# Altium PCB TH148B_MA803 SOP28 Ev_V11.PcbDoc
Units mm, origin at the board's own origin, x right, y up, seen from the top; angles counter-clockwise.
Board outline 72.39 x 53.59 mm, 2 copper layers (Top Layer, Bottom Layer); 44 components, 47 nets, 236 pads, 91 vias.
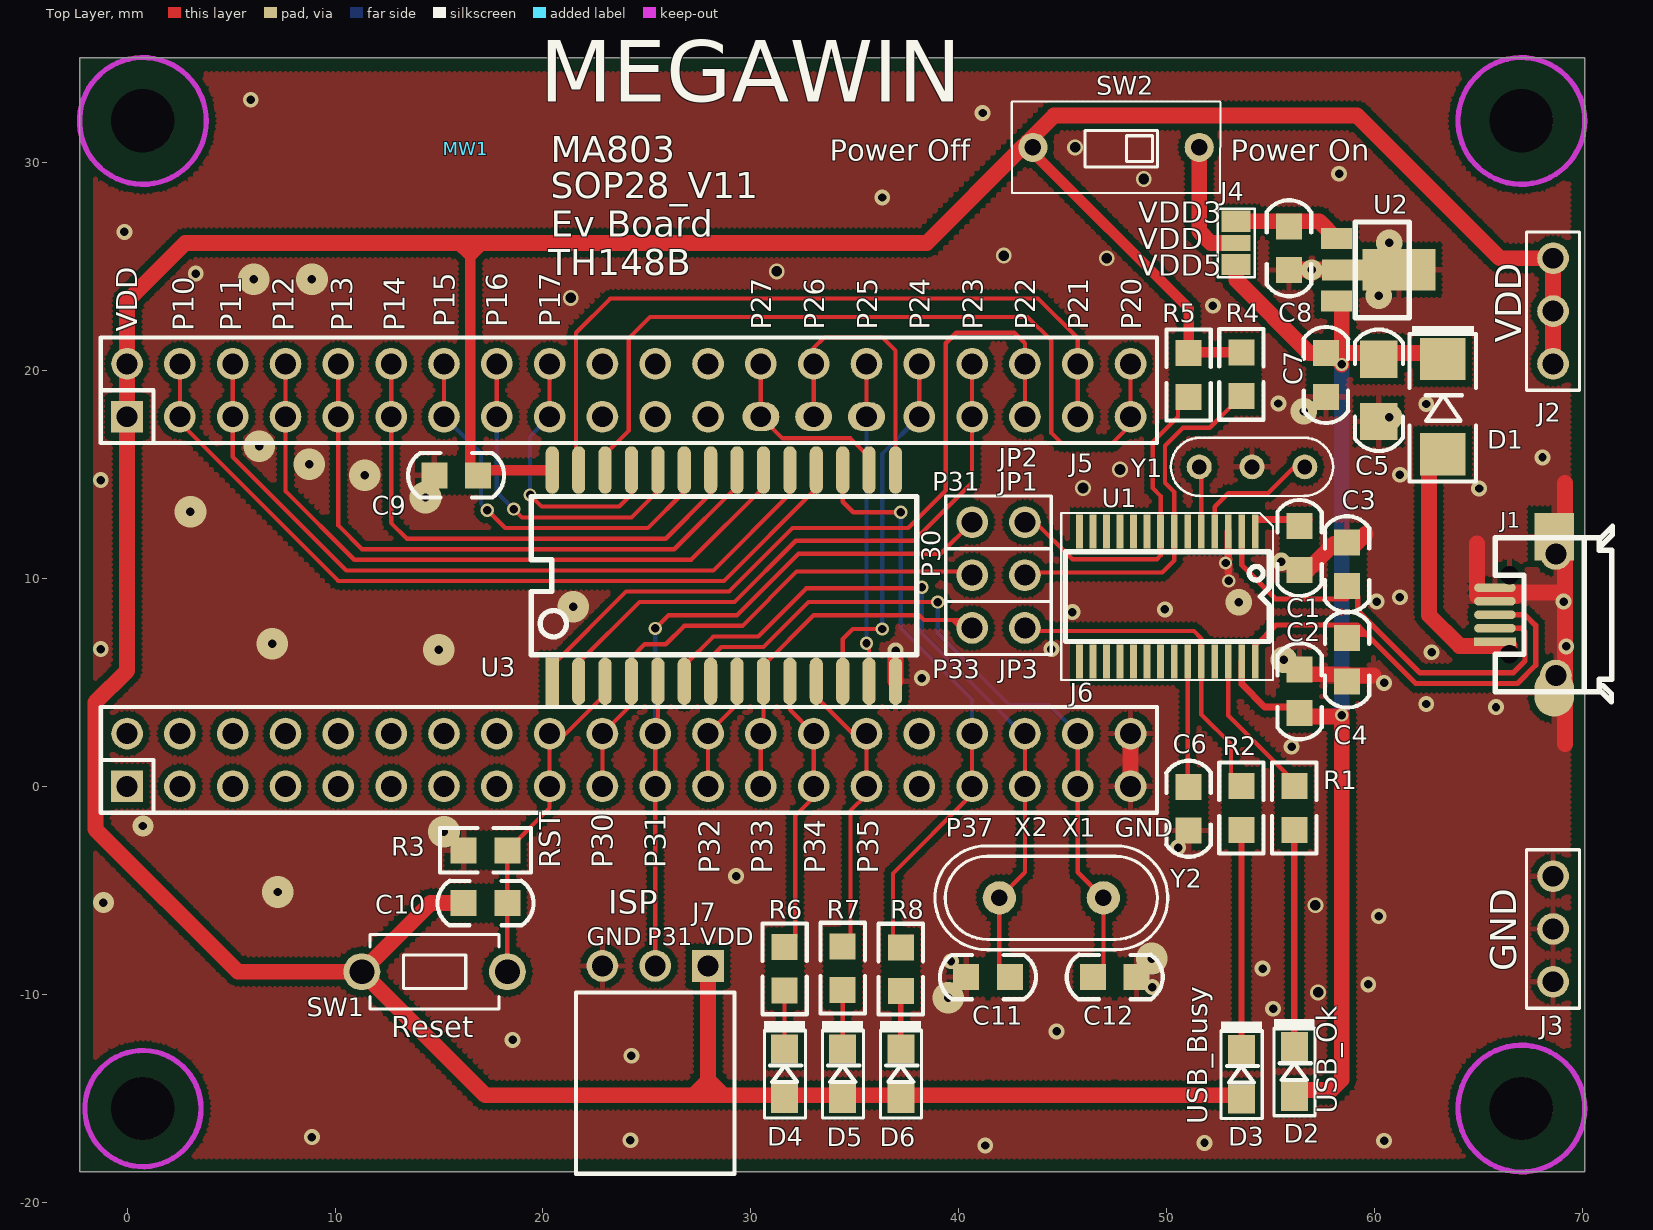
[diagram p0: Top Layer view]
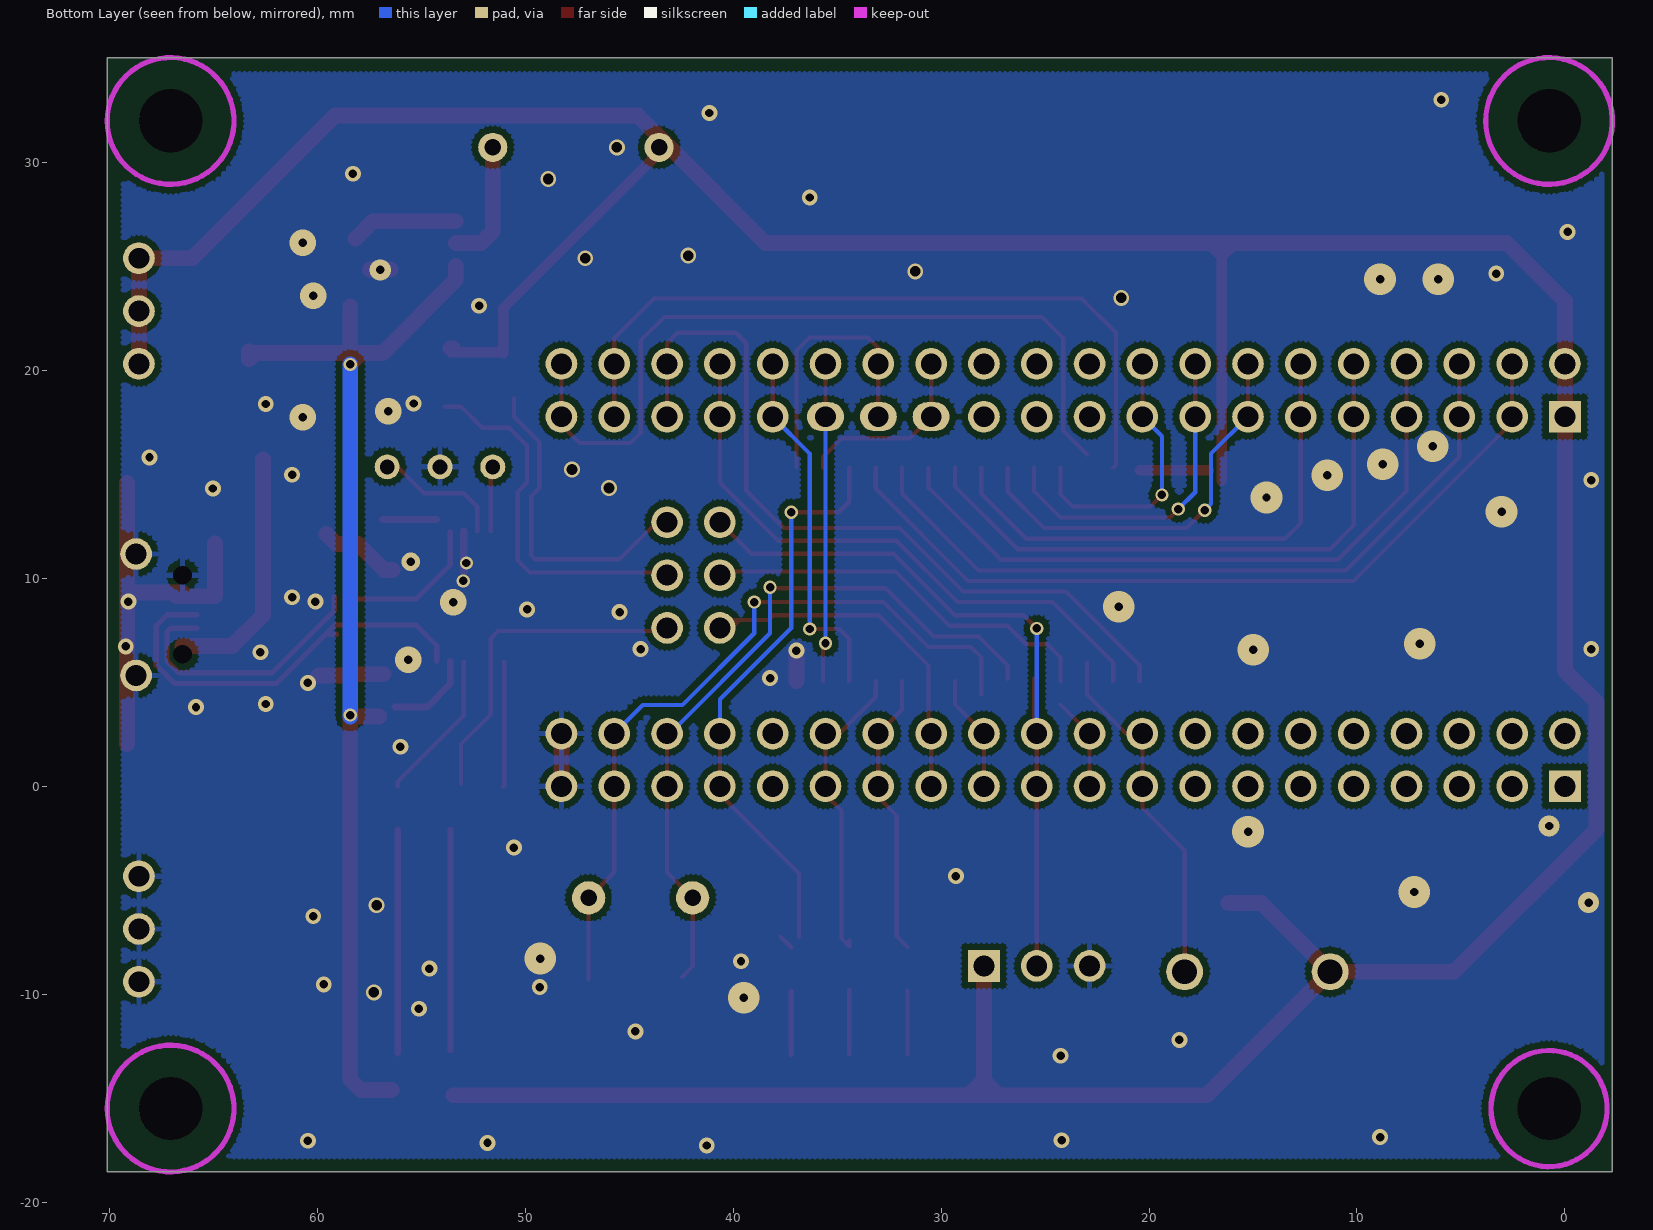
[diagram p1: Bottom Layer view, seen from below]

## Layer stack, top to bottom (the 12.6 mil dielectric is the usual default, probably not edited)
Top Layer: signal copper 0.0356
Dielectric: dielectric 0.32, FR-4, Dk 4.8
Bottom Layer: signal copper 0.0356

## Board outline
-2.286,-18.542 -2.286,35.052 70.104,35.052 70.104,-18.542

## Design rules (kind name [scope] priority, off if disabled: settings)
Clearance 12 [All] p1 off: gap=0.305
Clearance 10 [All] p2 off: gap=0.254
Clearance 6 [All] p3: gap=0.152
ComponentClearance [All] p1 off: gap=0.254 collisioncheckmode=3 verticalgap=0.254 showdistances=FALSE
HoleSize [All] p1: absolutevalues=TRUE maxlimit=12.7 minlimit=0.025 maxpercent=80.000 minpercent=20.000
MinimumSolderMaskSliver [All] p1 off: minsoldermaskwidth=0.254
PolygonConnect VIA [ISVIA] p1: connectstyle=Direct reliefconductorwidth=0.254 reliefentries=4 polygonreliefangle="90 Angle"
PolygonConnect [All] p2: connectstyle=Relief reliefconductorwidth=0.254 reliefentries=4 polygonreliefangle="90 Angle"
RoomDefinition "TH148B_MA803 SOP28 Ev_V10" [InComponentClass('TH148B_MA803 SOP28 Ev_V10')] p1: confinementstyle=ConfineIn formatcopy=TRUE lockcomponents=FALSE outline -6.35,-23.622 77.724,-23.622 77.724,42.291 -6.35,42.291
RoutingVias [All] p1: holewidth=0.406 width=0.635 viastyle="Through Hole" minholewidth=0.406 minwidth=0.61 maxholewidth=0.711 maxwidth=1.27
SilkToSilkClearance [All] p1 off: silktosilkclearance=0.254
SilkscreenOverComponentPads [All] p1 off: minsilkscreentomaskgap=0.254
SolderMaskExpansion [All] p1 off: expansion=0.102
Width [All] p1: maxlimit=5.08 minlimit=0.152 preferedwidth=0.254
23 further rules are at their usual default settings.

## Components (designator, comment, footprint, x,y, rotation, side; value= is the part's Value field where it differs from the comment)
C1 "4.7uF" 0805C 56.388,11.464 r270 top
C2 "0.1uF" 0805C 56.388,4.572 r270 top
C3 "15pF" 0805C 58.674,10.686 r90 top
C4 "15pF" 0805C 58.674,6.096 r270 top
C5 "4.7uF" 1206C 60.198,19.05 r270 top
C6 "0.1uF" 0805C 51.054,-1.075 r90 top
C7 "0.1uF" 0805C 57.658,19.787 r270 top
C8 "4.7uF" 0805C 55.88,25.883 r270 top
C9 "0.1uF" 0805C 15.824,14.961 r180 top
C10 "1u" 0805C 17.238,-5.613 r0 top
C11 "NC" 0805C 41.402,-9.169 r180 top
C12 "NC" 0805C 47.498,-9.169 r0 top
D1 "1N5817" D5817_SMD_1 63.28,18.263 r270 top
D2 "Yellow" 0805D 56.134,-13.716 r90 top
D3 "RED" 0805D 53.594,-13.843 r90 top
D4 "Green" 0805D 31.623,-13.82 r90 top
D5 "RED" 0805D 34.417,-13.82 r90 top
D6 "Green" 0805D 37.211,-13.82 r90 top
J1 "Micro USB母座" JACK_USB_SMD290X220P065 65.786,8.255 r180 top
J2 "*" PS3P254 68.58,20.32 r90 top
J3 "*" PS3P254 68.58,-4.318 r270 top
J4 "*" JUMP3_SMD 53.34,26.137 r90 top
J5 "*" PS20X2P254#1 0,17.78 r0 top locked
J6 "*" PS20X2P254#2 0,0 r0 top locked
J7 "*" PS3P254f_90 27.94,-8.636 r180 top
JP1 "JUMPER2" PS2P254 40.64,10.16 r0 top
JP2 "JUMPER2" PS2P254 40.64,12.7 r0 top
JP3 "JUMPER2" PS2P254 40.64,7.62 r0 top
MW1 "MW-A4" MEGAWIN_T 16.286,30.663 r0 top
R1 "1K" 0805R 56.134,-1.041 r270 top
R2 "1K" 0805R 53.594,-1.041 r270 top
R3 "47K" 0805R 17.238,-3.073 r0 top
R4 "4.7K" 0805R 53.594,19.821 r270 top
R5 "4.7K" 0805R 51.054,19.787 r270 top
R6 "1K" 0805R 31.623,-8.774 r270 top
R7 "1K" 0805R 34.417,-8.74 r270 top
R8 "1K" 0805R 37.211,-8.788 r270 top
SW1 "SW TACT-SPST" SW_T_2P 14.788,-8.915 r0 top
SW2 "-" DIP2_SW 51.562,30.734 r180 top
U1 "MA101_TSSOP28" TSSOP28_170P065 50.034,9.132 r180 top
U2 "AIC1734-33(SOT-89)" SOT89 58.166,24.843 r270 top
U3 "MA803 (SOP-28)" SO28_300P127 28.702,10.135 r0 top locked
Y1 "6MHz" X3P 56.642,15.367 r180 top (schematic designator X1)
Y2 "NC" X49U 44.45,-5.359 r0 top (schematic designator X2)

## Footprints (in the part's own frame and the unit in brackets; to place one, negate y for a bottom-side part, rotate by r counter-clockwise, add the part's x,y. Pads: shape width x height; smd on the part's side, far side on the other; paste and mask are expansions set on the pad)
0805C [mm]
  rect 1.25x1.25 smd: 1(-1.05,0) 2(1.05,0)
  silkscreen extent -2.31,-1.07 2.31,1.07
0805D [mm]
  rect 1.4x1.3 smd: 1(-1.192,0) 2(1.192,0)
  silkscreen extent -2.12,-1 2.53,0.98
0805R [mm]
  rect 1.25x1.25 smd: 1(-1.05,0) 2(1.05,0)
  silkscreen extent -2.18,-1.07 2.18,1.07
1206C [mm]
  rect 1.8x1.8 smd: 1(-1.5,0) 2(1.5,0)
  silkscreen extent -2.92,-1.15 2.92,1.16
D5817_SMD_1 [mil]
  rect 80x86.61 smd: 1(90,0) 2(-90,0)
  silkscreen extent -153,-63 142,63
DIP2_SW [mm]
  round 1.4 hole 0.8: 1(0,0) 2(8,0)
  silkscreen extent -1.02,-2.2 9.02,2.2
JACK_USB_SMD290X220P065 [mm]
  rect 1.9x1.8 on Mech2: 0(-2.85,-1.15) 0(-2.85,1.15)
  round 0.8 hole 0.9 unplated: 1(-0.7,1.9) 5(-0.7,-1.9)
  rect 2x0.4 smd: 1(0,1.3)
  oval 2x0.4 smd: 2(0,0.65) 3(0,0) 4(0,-0.65) 5(0,-1.3)
  round 1.524 hole 1: 5(-2.931,2.921) 5(-2.931,-2.921)
  oval 1.9x2.3 smd: 5(-2.85,3.75)
  rect 1.9x2.3 smd: 5(-2.85,-3.75)
  silkscreen extent -5.65,-4.25 -0.01,4.2
JUMP3_SMD [mil]
  rect 40x55 smd: 1(-41,0) 3(41,0)
  rect 30x55 smd: 2(0,0)
  silkscreen extent -65,-35 65,35
MEGAWIN_T [mm]
PS2P254 [mil]
  round 60 hole 39.37: 1(0,0) 2(100,0)
  silkscreen extent -50,-50 150,50
PS3P254 [mil]
  round 60 hole 39.37: 1(0,0) 2(100,0) 3(200,0)
  silkscreen extent -50,-50 250,50
PS3P254f_90 [mil]
  rect 60x60 hole 39.37: 1(0,0)
  round 60 hole 39.37: 2(100,0) 3(200,0)
  silkscreen extent -50,50 250,394
PS20X2P254#1 [mil]
  rect 60x60 hole 39.37: 1(0,0)
  round 60 hole 39.37: 2(0,100) 3(100,0) 4(100,100) 5(200,0) 6(200,100) 7(300,0) 8(300,100) 9(400,0) 10(400,100) 11(500,0) 12(500,100) 13(600,0) 14(600,100) 15(700,0) 16(700,100) 17(800,0) 18(800,100) 19(900,0) 20(900,100) 21(1000,0) 22(1000,100) 23(1100,0) 24(1100,100) 26(1200,100) 28(1300,100) 30(1400,100) 31(1500,0) 32(1500,100) 33(1600,0) 34(1600,100) 35(1700,0) 36(1700,100) 37(1800,0) 38(1800,100) 39(1900,0) 40(1900,100)
  oval 70x55 hole 39.37: 25(1200,0) 27(1300,0) 29(1400,0)
  silkscreen extent -50,-50 1950,150
PS20X2P254#2 [mil]
  rect 60x60 hole 39.37: 1(0,0)
  round 60 hole 39.37: 2(0,100) 3(100,0) 4(100,100) 5(200,0) 6(200,100) 7(300,0) 8(300,100) 9(400,0) 10(400,100) 11(500,0) 12(500,100) 13(600,0) 14(600,100) 15(700,0) 16(700,100) 17(800,0) 18(800,100) 19(900,0) 20(900,100) 21(1000,0) 22(1000,100) 23(1100,0) 24(1100,100) 25(1200,0) 26(1200,100) 27(1300,0) 28(1300,100) 29(1400,0) 30(1400,100) 31(1500,0) 32(1500,100) 33(1600,0) 34(1600,100) 35(1700,0) 36(1700,100) 37(1800,0) 38(1800,100) 39(1900,0) 40(1900,100)
  silkscreen extent -50,-50 1950,150
SO28_300P127 [mil]
  rect 25x90 smd: 1(-325,-200)
  oval 25x90 smd: 2(-275,-200) 3(-225,-200) 4(-175,-200) 5(-125,-200) 6(-75,-200) 7(-25,-200) 8(25,-200) 9(75,-200) 10(125,-200) 11(175,-200) 12(225,-200) 13(275,-200) 14(325,-200) 15(325,200) 16(275,200) 17(225,200) 18(175,200) 19(125,200) 20(75,200) 21(25,200) 22(-25,200) 23(-75,200) 24(-125,200) 25(-175,200) 26(-225,200) 27(-275,200) 28(-325,200)
  silkscreen extent -365,-150 365,150
SOT89 [mm]
  rect 1.016x1.5 smd: 1(-1.5,0) 3(1.5,0)
  rect 2x3.5 smd: 2(0,3)
  rect 1.016x2.6 smd: 2(0,0.6)
  silkscreen extent -2.3,0.9 2.3,3.5
SW_T_2P [mm]
  round 1.778 hole 1.2: 1(-3.5,0) 2(3.5,0)
  silkscreen extent -3.1,-1.8 3.1,1.8
TSSOP28_170P065 [mil]
  rect 13x65 smd: 1(-166.34,-123) 2(-140.75,-123) 3(-115.16,-123) 4(-89.57,-123) 5(-63.98,-123) 6(-38.39,-123) 7(-12.79,-123) 8(12.8,-123) 9(38.39,-123) 10(63.98,-123) 11(89.57,-123) 12(115.16,-123) 13(140.75,-123) 14(166.34,-123) 15(166.34,123) 16(140.75,123) 17(115.16,123) 18(89.57,123) 19(63.98,123) 20(38.39,123) 21(12.8,123) 22(-12.79,123) 23(-38.39,123) 24(-63.98,123) 25(-89.57,123) 26(-115.16,123) 27(-140.75,123) 28(-166.34,123)
  silkscreen extent -200,-158 201,158
X3P [mm]
  round 1.2 hole 0.711: 1(0,0) 2(5.08,0) 3(2.54,0)
  silkscreen extent -1.36,-1.4 6.44,1.4
X49U [mm]
  round 1.6 hole 0.8: 1(-2.5,0) 2(2.5,0)
  silkscreen extent -5.6,-2.5 5.6,2.5

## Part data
C1 C5 C8: library part CAP
C2 C3 C4 C6 C7 C9: library part "CAP NP"
C10: library part C
C11 C12: library part "C NP"
D1: library part DIODE_ZD, "Schottky Diode"
D2 D3 D4 D5 D6: library part LED
J1: library part CON5, "Connector"
J2 J3 J4 J7: library part CON3
J5 J6: library part CON40A
R1 R2 R4 R5 R6 R7 R8: library part R_Dup1
R3: library part R
SW2: library part SW-2
U2: library part AIC1734-33(SOT-89)_0
U3: library part MPC82L54(TSSOP28)
Y1: library part CRYSTAL_RC
Y2: library part CRYSTAL

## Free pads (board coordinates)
  round 3 hole 3.048 unplated: 0(0.762,-15.494) 0(0.762,32.004) 0(67.056,-15.494) 0(67.056,32.004)

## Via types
v1: diameter 0.762, hole 0.406, Top Layer to Bottom Layer, tented both sides, 44 vias
v2: diameter 1.524, hole 0.406, Top Layer to Bottom Layer, tented both sides, 14 vias
v3: diameter 0.635, hole 0.406, Top Layer to Bottom Layer, tented both sides, 13 vias
v4: diameter 0.762, hole 0.508, Top Layer to Bottom Layer, tented both sides, 10 vias
v5: diameter 1.27, hole 0.406, Top Layer to Bottom Layer, tented both sides, 6 vias
v6: diameter 1.016, hole 0.406, Top Layer to Bottom Layer, tented both sides, 3 vias
v7: diameter 0.889, hole 0.406, Top Layer to Bottom Layer, tented both sides, 1 vias

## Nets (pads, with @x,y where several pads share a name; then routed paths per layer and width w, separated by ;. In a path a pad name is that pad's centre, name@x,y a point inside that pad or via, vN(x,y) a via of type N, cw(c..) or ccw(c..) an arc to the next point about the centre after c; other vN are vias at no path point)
D+: C4.1 J1.3 U1.28 | length 20.8
  Top Layer w0.254: U1.28 54.259,6.761 55.262,7.764 58.674,7.764 59.165,7.764 59.228,7.701 61.976,4.953 66.871,4.953 67.742,5.824 67.742,7.745 67.232,8.255 J1.3 ; C4.1@59.08,7.315 59.571,7.315
D-: C3.1 J1.2 U1.2 | length 20.5
  Top Layer w0.254: U1.2 53.609,10.653 55.245,9.017 C3.1@58.674,9.017 ; C3.1@59.182,9.119 59.182,8.465 62.186,5.461 66.661,5.461 67.234,6.034 67.234,7.438 67.067,7.605 J1.2
GND_POWER: C1.2 C2.1 C3.2 C4.2 C5.2 C6.1 C7.2 C8.2 C9.2 C11.2 C12.2 J1.4 J1.5 J3.1 J3.2 J3.3 J6.39 J6.40 J7.3 R3.1 U1.3 U2.2 U3.14 Y1.3 | length 33.6
  Top Layer w0.381: 52.959,10.312 v3@52.959,10.566 ; U1.3 52.959,10.744 v3@52.959,10.566 ; v3@52.984,10.541 v3@52.959,10.566
  Top Layer w0.762: U3.14 v1(36.957,6.528) ; J6.39 J6.40 ; C1.2 56.794,10.414 58.039,11.659 58.674,11.659 59.089,11.659 59.563,12.133 ; C8.2@56.473,24.867 56.972,24.867 U2.2@57.48,24.867 ; C2.1@56.82,5.393 C4.2@58.674,5.393 ; C4.2@58.42,5.334 58.674,5.334 59.944,5.334 ; 64.919,9.145 65.786,9.145 66.784,9.145 ; 64.919,9.211 64.919,9.555 64.919,11.677 ; 66.511,9.323 68.977,9.323 ; 69.161,2.032 69.161,4.505 69.161,5.334 69.161,6.731 69.161,8.89 69.161,11.176 69.161,12.005 69.161,14.598
  other v1: 41.275,-17.272 51.816,-17.145 60.452,-17.043 24.206,-17.018 8.89,-16.866 24.257,-12.954 18.542,-12.192 44.704,-11.786 55.118,-10.693 49.301,-9.652 59.69,-9.525 54.61,-8.763 39.624,-8.407 60.198,-6.248 29.286,-4.318 50.546,-2.946 56.007,1.905 65.837,3.81 62.484,3.962 60.452,4.978 38.227,5.207 62.738,6.452 -1.27,6.604 44.45,6.604 69.215,6.731 45.466,8.382 49.911,8.509 60.096,8.89 69.088,8.89 61.214,9.093 65.024,14.326 -1.27,14.732 61.214,14.986 68.072,15.824 62.484,18.39 55.372,18.415 52.222,23.114 3.302,24.663 -0.127,26.67 36.322,28.321 58.293,29.464 41.148,32.385 5.944,33.02
  other v2: 39.497,-10.16 49.276,-8.28 7.239,-5.08 15.24,-2.184 14.986,6.579 6.985,6.858 21.463,8.636 3.048,13.208 14.351,13.894 11.43,14.961 8.763,15.494 6.35,16.358 6.096,24.384 8.89,24.384
  other v3: 52.984,9.881 52.832,10.744
  other v4: 57.277,-9.906 57.15,-5.715 45.974,14.351 47.752,15.24 21.336,23.495 31.242,24.765 47.117,25.4 42.164,25.527 48.895,29.21 45.593,30.734
  other v5: 55.626,6.096 53.467,8.865 60.706,17.755 56.591,18.047 60.198,23.597 60.706,26.137
  other v6: -1.143,-5.588 0.762,-1.905 56.972,24.841
  other v7: 55.499,10.795
MA101_RX: JP2.2 R5.2 U1.8 | length 15.6
  Top Layer w0.203: JP2.2 43.688,12.7 45.466,10.922 49.53,10.922 49.709,11.101 U1.8 49.709,13.97 49.328,14.351 49.328,16.562 50.546,17.78 R5.2@50.546,18.669
MA101_TX: JP1.2 R4.2 U1.7 | length 17.7
  Top Layer w0.203: JP1.2@43.307,10.287 49.784,10.287 50.359,10.862 U1.7 50.359,14.157 49.911,14.605 49.911,16.383 50.775,17.247 52.07,17.247 53.086,18.263 53.594,18.263 R4.2@53.848,18.263
NetC1_1: C1.1 U1.1 | length 2.6
  Top Layer w0.33: U1.1@54.259,12.827 56.388,12.827 C1.1@56.862,12.827
NetC6_2: C6.2 U1.23 | length 7.3
  Top Layer w0.203: 51.009,3.601 51.009,4.547 ; 51.009,4.856 51.009,4.547 ; U1.23 51.009,4.547 ; C6.2 51.009,0.02 51.009,4.547
NetD1_1: D1.1 J1.1 | length 12
  Top Layer w0.762: D1.1@62.611,15.717 62.611,8.23 64.084,6.756 65.786,6.756 66.486,6.756 J1.1@66.497,6.756
NetD2_2: D2.2 R1.2 | length 10.7
  Top Layer w0.305: D2.2@56.134,-12.827 D2.2 R1.2
NetD3_2: D3.2 R2.2 | length 10.6
  Top Layer w0.305: D3.2@53.594,-12.7 D3.2 R2.2
NetD4_2: D4.2 R6.2 | length 3.1
  Top Layer w0.203: D4.2@31.623,-12.882 D4.2 R6.2
NetD5_2: D5.2 R7.2 | length 3.1
  Top Layer w0.203: D5.2@34.417,-12.882 D5.2 R7.2
NetD6_2: D6.2 R8.2 | length 3
  Top Layer w0.254: D6.2@37.211,-12.882 D6.2 R8.2
NetJ4_2: J4.2 SW2.1 | length 8.7
  Top Layer w0.762: 51.562,27.206 51.562,29.845 ; SW2.1 51.562,29.845 ; J4.2 52.124,26.137 51.562,26.698 51.562,29.845
NetU1_4: U1.4 Y1.1 | length 6.3
  Top Layer w0.203: U1.4 52.309,13.447 52.959,14.097 54.864,14.097 56.134,15.367 Y1.1
NetU1_5: U1.5 Y1.2 | length 3.2
  Top Layer w0.203: Y1.2@51.278,15.083 Y1.2 ; U1.5 Y1.2@51.659,15.083
P10: J5.3 J5.4 U3.18 | length 39.4
  Top Layer w0.203: J5.4 J5.3 2.54,17.501 10.16,9.881 28.702,9.881 33.147,14.326 U3.18 U3.18@33.147,15.342
P11: J5.5 J5.6 U3.19 | length 36.3
  Top Layer w0.203: J5.6 J5.5 5.08,15.85 10.541,10.389 28.194,10.389 31.877,14.072 U3.19 U3.19@31.877,15.342
P12: J5.7 J5.8 U3.20 | length 32.9
  Top Layer w0.203: J5.8 J5.7 7.62,14.199 10.922,10.897 27.127,10.897 U3.20@30.607,14.376 ; U3.20@30.607,14.326 U3.20@30.607,14.376 ; U3.20@30.607,15.342 U3.20 U3.20@30.607,14.376
P13: J5.9 J5.10 U3.21 | length 29.6
  Top Layer w0.203: J5.10 J5.9 10.16,12.548 11.303,11.405 26.314,11.405 29.337,14.427 U3.21 U3.21@29.337,15.342
P14: J5.11 J5.12 U3.22 | length 25.5
  Top Layer w0.203: J5.12 J5.11 12.7,12.675 13.462,11.913 25.908,11.913 28.067,14.072 U3.22 U3.22@28.067,15.342
P15: J5.13 J5.14 U3.23 | length 19.6
  Top Layer w0.203: J5.13 J5.14 ; v3(17.323,13.284) 18.186,12.421 25.044,12.421 26.797,14.173 U3.23 U3.23@26.797,15.342
  Bottom Layer w0.203: J5.13 17.018,16.002 17.018,13.589 v3(17.323,13.284)
P16: J5.15 J5.16 U3.24 | length 16.1
  Top Layer w0.203: J5.15 J5.16 ; v3(18.593,13.335) 18.999,12.929 24.257,12.929 25.527,14.199 U3.24 U3.24@25.527,15.342
  Bottom Layer w0.203: J5.15 17.78,14.148 v3(18.593,13.335)
P17: J5.17 J5.18 U3.25 | length 13.3
  Top Layer w0.203: v3(19.38,14.021) 19.939,13.462 23.673,13.462 24.257,14.046 U3.25 U3.25@24.257,15.342 ; J5.17 J5.18
  Bottom Layer w0.203: v3(19.38,14.021) 19.38,16.84 J5.17
P20: J5.39 J5.40 U3.26 | length 39
  Top Layer w0.203: U3.26@22.987,15.977 24.13,17.12 24.13,21.565 25.146,22.581 43.307,22.581 44.45,21.438 44.45,16.993 44.933,16.51 47.396,16.51 48.26,17.374 J5.39 J5.40
P21: J5.37 J5.38 U3.27 | length 35.9
  Top Layer w0.203: U3.27@21.717,15.342 21.59,15.469 21.59,21.819 23.241,23.47 43.815,23.47 45.72,21.565 J5.38 J5.37
P22: J5.35 J5.36 U3.1 | length 38
  Top Layer w0.203: U3.1 20.447,5.817 24.003,9.373 28.956,9.373 32.004,12.421 37.567,12.421 39.37,14.224 39.37,21.311 39.878,21.819 42.672,21.819 43.18,21.311 J5.36 J5.35
P23: J5.33 J5.34 U3.2 | length 29.6
  Top Layer w0.203: U3.2 21.717,5.944 24.638,8.865 29.21,8.865 32.156,11.811 37.846,11.811 40.64,14.605 J5.33 J5.34 J5.34@40.279,19.959
P24: J5.31 J5.32 U3.12 | length 18.2
  Top Layer w0.203: U3.12 34.417,7.087 34.9,7.569 v3(36.322,7.569) ; J5.31 J5.32
  Bottom Layer w0.203: v3(36.322,7.569) 36.322,16.002 J5.31 J5.31@37.719,17.399
P25: J5.29 J5.30 U3.13 | length 15.3
  Top Layer w0.203: J5.29 J5.30 ; U3.13 v3@35.687,6.883
  Bottom Layer w0.203: v3(35.56,6.883) J5.29
P26: J5.27 J5.28 U3.15 | length 13.3
  Top Layer w0.203: J5.27 J5.28 33.02,21.082 33.528,21.59 36.322,21.59 36.957,20.955 U3.15@36.957,15.342
P27: J5.25 J5.26 U3.16 | length 9.1
  Top Layer w0.203: J5.26 J5.25 31.521,16.739 34.798,16.739 35.687,15.85 U3.16@35.687,15.342
P30_RXD: J6.19 J6.20 JP1.1 U3.4 | length 23.5
  Top Layer w0.203: J6.19 J6.20 ; J6.20@23.1,2.78 U3.4@24.257,3.937 ; U3.4@24.257,5.182 U3.4 24.257,6.198 24.892,6.833 25.908,6.833 26.797,7.722 29.591,7.722 32.199,10.33 JP1.1@40.64,10.33
P31_TXD: J6.21 J6.22 J7.2 JP2.1 U3.5 | length 36.1
  Top Layer w0.203: J7.2@25.4,-8.661 J7.2 J6.21 J6.22 ; v3(25.4,7.595) 26.035,8.23 29.337,8.23 32.293,11.186 39.126,11.186 JP2.1 ; J6.22@25.527,2.667 U3.5 U3.5@25.527,5.182
  Bottom Layer w0.203: J6.22 v3(25.4,7.595)
P32: J6.23 J6.24 U3.8 | length 5.6
  Top Layer w0.203: J6.23 J6.24 29.337,3.937 U3.8
P33: J6.25 J6.26 JP3.1 U3.9 | length 18.1
  Top Layer w0.203: J6.25 J6.26 30.607,2.667 U3.9 30.607,5.817 33.02,8.23 38.1,8.23 38.329,8.001 39.7,8.001 ; JP3.1@40.107,7.595 39.7,8.001 ; JP3.1@41.148,8.001 40.64,8.001 39.7,8.001
P34: J6.27 J6.28 R6.1 U3.10 | length 13.8
  Top Layer w0.203: R6.1 32.131,-7.216 32.131,-1.422 33.02,-0.533 J6.27 J6.28 31.877,3.683 U3.10
P35: J6.29 J6.30 R7.1 U3.11 | length 14.9
  Top Layer w0.203: U3.11 33.147,4.293 34.9,2.54 J6.30 J6.29 35.56,-0.406 34.798,-1.168 34.798,-7.309 R7.1 R7.1@34.417,-7.417
P37: J6.33 J6.34 R8.1 U3.17 | length 28.8
  Top Layer w0.203: U3.17@34.417,15.342 U3.17 34.417,13.691 34.925,13.183 v3(37.211,13.183) ; R8.1@36.83,-7.23 36.83,-4.186 ; 36.835,-4.186 40.64,-0.381 J6.33 J6.34 ; R8.1 R8.1@37.719,-7.23
  Bottom Layer w0.203: v3@37.084,13.183 v3@37.148,13.119 ; v3@37.211,13.119 37.211,7.62 40.64,4.191 J6.34
RST: C10.2 J6.17 J6.18 R3.2 SW1.2 U3.3 | length 16.4
  Top Layer w0.203: SW1.2 C10.2 R3.2 20.32,-1.041 J6.17 J6.18 ; 21.107,2.54 22.987,4.42 U3.3 ; U3.3@22.987,5.182 U3.3@22.987,5.944
USB_BUSY: JP3.2 R2.1 U1.24 | length 17.3
  Top Layer w0.203: JP3.2@43.332,7.468 49.657,7.468 ; 50.673,7.468 49.657,7.468 ; 51.054,7.468 51.308,7.468 ; R2.1@53.086,0.127 53.086,2.032 51.659,3.459 U1.24 51.659,7.117 51.308,7.468 ; 49.657,7.468 51.308,7.468
USB_OK: R1.1 U1.26 | length 7.3
  Top Layer w0.203: U1.26 52.959,3.404 56.134,0.229 R1.1
VDD: C9.1 C10.1 D3.1 D4.1 D5.1 D6.1 J2.1 J2.2 J2.3 J5.1 J5.2 J7.1 R4.1 R5.1 SW1.1 SW2.2 U3.28 | length 214.7
  Top Layer w0.381: 15.57,26.264 15.697,26.137 ; 15.71,26.175 15.748,26.137 16.51,25.375 17.272,26.137 17.297,26.162 ; 17.297,26.137 17.424,26.264 ; 26.975,-14.856 27.915,-13.917 ; 28.016,-13.917 28.956,-14.856
  Top Layer w0.508: C9.1@16.51,14.707 16.51,14.961 16.51,25.375 16.51,25.883 ; C9.1@17.128,15.215 U3.28 ; SW2.2@43.054,30.734 43.307,30.734 43.434,30.607 51.054,22.987 R5.1 ; R5.1@51.088,20.871 R4.1
  Top Layer w0.762: C10.1 14.59,-5.613 SW1.1 ; J7.1@27.94,-8.661 27.94,-14.856 ; R4.1@53.466,21.057 R4.1@53.594,21.057 ; D3.1@53.467,-14.856 37.211,-14.856 34.417,-14.856 31.623,-14.856 28.956,-14.856 27.94,-14.856 ; J2.1 J2.2 J2.3 66.015,25.4 59.157,32.258 44.578,32.258 43.308,30.988 43.054,30.734 38.457,26.137 17.297,26.137 17.272,26.137 15.748,26.137 15.697,26.137 2.794,26.137 0,23.343 J5.2 J5.1 0,5.563 -1.524,4.039 -1.524,-2.057 5.334,-8.915 SW1.1 ; SW1.1 17.229,-14.856 26.975,-14.856 27.94,-14.856
VDD3: C8.1 J4.3 U2.1 | length 5.2
  Top Layer w0.762: J4.3 55.88,27.178 57.331,27.178 U2.1
VDD5: C2.2 C5.1 C7.1 D1.2 D2.1 J4.1 U1.27 U2.3 | length 57.8
  Top Layer w0.33: U1.27 53.609,4.913 54.712,3.81 C2.2@56.261,3.81
  Top Layer w0.762: J4.1@53.34,25.019 53.34,24.359 56.862,20.837 C7.1@57.624,20.837 ; D2.1@56.437,-14.605 57.912,-14.605 58.42,-14.097 v3@58.42,3.361 ; 57.023,3.361 v3@58.42,3.361 ; C7.1@57.641,20.82 C7.1@57.624,20.837 ; v3(58.42,3.429) v3@58.42,3.361 ; v3(58.42,20.295) 58.42,20.329 C7.1@57.912,20.837 ; U2.3@58.42,23.089 58.42,20.837 ; D1.2@63.28,20.929 D1.2 62.992,20.837 60.198,20.837 58.42,20.837 ; C7.1@57.624,20.837 C7.1 C7.1@57.912,20.837 ; C7.1@57.912,20.837 58.42,20.837
  Bottom Layer w0.762: v3@58.42,3.361 v3(58.42,3.429) v3(58.42,20.295)
XTAL1: C12.1 J6.37 J6.38 U3.7 Y2.2 | length 37.1
  Top Layer w0.203: U3.7@28.067,4.42 U3.7 ; U3.7@28.067,5.182 U3.7 ; v3(38.989,8.865) 32.766,8.865 30.607,6.706 28.575,6.706 28.067,6.198 U3.7 ; J6.38 J6.37 45.72,-4.129 Y2.2 46.956,-5.365 46.956,-9.169 C12.1@46.956,-9.271
  Bottom Layer w0.203: 38.989,7.874 38.989,8.509 ; v3(38.989,8.865) 38.989,8.509 ; J6.38 44.351,3.909 42.446,3.909 38.989,7.366 38.989,8.509
XTAL2: C11.1 J6.35 J6.36 U3.6 Y2.1 | length 35.1
  Top Layer w0.203: U3.6@26.797,5.182 26.797,5.817 28.194,7.214 30.353,7.214 32.664,9.525 v3@38.227,9.525 ; C11.1 41.95,-8.667 Y2.1 43.18,-4.129 J6.35 J6.36
  Bottom Layer w0.203: v3@38.227,9.525 38.227,7.366 42.926,2.667 J6.36@43.18,2.667
  other v3: 38.227,9.576
pads on no net: J1.0 J5.19 J5.20 J5.21 J5.22 J5.23 J5.24 J6.1 J6.2 J6.3 J6.4 J6.5 J6.6 J6.7 J6.8 J6.9 J6.10 J6.11 J6.12 J6.13 J6.14 J6.15 J6.16 J6.31 J6.32 U1.6 U1.9 U1.10 U1.11 U1.12 U1.13 U1.14 U1.15 U1.16 U1.17 U1.18 U1.19 U1.20 U1.21 U1.22 U1.25

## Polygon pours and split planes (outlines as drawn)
GND_POWER on Top Layer "Bottom Layer-No Net" (hatched 90Degree grid 0.254 track 0.254, remove dead copper, pour order 1001): -1.524,-17.805 69.342,-17.805 69.342,34.29 -1.524,34.29
GND_POWER on Bottom Layer "Bottom Layer-No Net" (hatched 90Degree grid 0.254 track 0.254, remove dead copper, pour order 1001): -1.778,-17.805 69.342,-17.805 69.342,34.29 -1.778,34.29

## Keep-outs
Keep-Out Layer:
  circle w0.254: c67.056,-15.494 r3.048
  circle w0.254: c0.762,32.004 r3.048
  circle w0.254: c0.762,-15.494 r2.794
  circle w0.254: c67.056,32.004 r3.048

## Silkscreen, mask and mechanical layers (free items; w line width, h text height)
Top Overlay:
  text "Power Off" at 33.782,30.099 h1.02
  text "Power On" at 53.086,30.099 h1.02
  text "MA803" at 20.371,30.023 h1.27
  text "SOP28_V11" at 20.371,28.296 h1.27
  text "VDD3" at 48.622,27.102 h1.02
  text "Ev Board" at 20.371,26.441 h1.27
  text "VDD" at 48.622,25.832 h1.02
  text "TH148B" at 20.244,24.587 h1.27
  text "VDD5" at 48.622,24.562 h1.02
  text "P15" at 15.747,22.071 h1.02 r90
  text "P16" at 18.287,22.071 h1.02 r90
  text "P17" at 20.827,22.071 h1.02 r90
  text "P27" at 30.988,21.971 h0.97 r90
  text "P26" at 33.528,21.971 h0.97 r90
  text "P25" at 36.068,21.971 h0.97 r90
  text "P24" at 38.608,21.971 h0.97 r90
  text "P23" at 41.148,21.971 h0.97 r90
  text "P22" at 43.688,21.971 h0.97 r90
  text "P21" at 46.228,21.971 h0.97 r90
  text "P20" at 48.768,21.971 h0.97 r90
  text "P10" at 3.2,21.895 h1.02 r90
  text "P11" at 5.486,21.895 h1.02 r90
  text "P12" at 8.026,21.895 h1.02 r90
  text "P13" at 10.82,21.895 h1.02 r90
  text "P14" at 13.36,21.895 h1.02 r90
  text "VDD" at 0.483,21.869 h1.02 r90
  text "VDD" at 67.056,21.336 h1.27 r90
  text "P31" at 38.735,14.224 h0.89
  text "P30" at 39.116,10.033 h0.89 r90
  text "P33" at 38.735,5.207 h0.89
  text "X2" at 42.672,-2.388 h0.89
  text "P37" at 39.37,-2.413 h0.89
  text "X1" at 44.958,-2.413 h0.9
  text "GND" at 47.498,-2.413 h0.9
  text "RST" at 20.828,-3.937 h1.02 r90
  text "P30" at 23.368,-3.937 h1.02 r90
  text "P31" at 25.908,-3.937 h1.02 r90
  text "P32" at 28.499,-4.191 h1.02 r90
  text "P33" at 31.039,-4.191 h1.02 r90
  text "P34" at 33.579,-4.191 h1.02 r90
  text "P35" at 36.119,-4.191 h1.02 r90
  text "ISP" at 23.139,-6.121 h1.14
  text "GND" at 22.098,-7.645 h0.84
  text "P31" at 25.019,-7.645 h0.84
  text "VDD" at 27.559,-7.645 h0.84
  text "GND" at 66.802,-8.89 h1.27 r90
  text "Reset" at 12.7,-12.065 h1.02
  text "USB_Ok" at 58.166,-15.748 h0.97 r90
  text "USB_Busy" at 51.943,-16.256 h0.97 r90
Mechanical 1:
  the board outline again, w0.33

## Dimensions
-2.286,35.052 to -2.286,-18.542 on Top Overlay
-2.286,-18.542 to 70.104,-18.542 on Top Overlay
